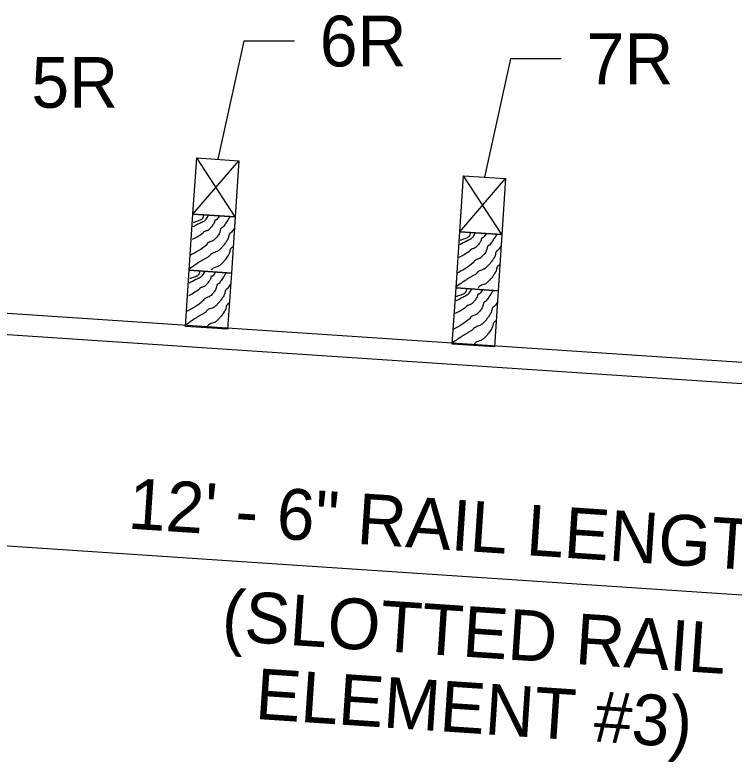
# Model space of a CAD drawing. Extents: x 1312564.2 to 1312581.5, y 1207298.4 to 1207352.6.
# Drawn here: x 1312568.33 to 1312569.46, y 1207300.555 to 1207301.729 of the extents above; entities that cross this region are included whole.
import ezdxf

# ---------------------------------------------------------------- set-up
doc = ezdxf.new("R2010")
doc.units = 0
for name, color, linetype in [('Level 13', 7, 'Continuous'), ('Level 14', 7, 'Continuous'), ('Level 15', 7, 'Continuous'), ('Level 20', 7, 'Continuous')]:
    doc.layers.add(name, color=color, linetype=linetype)

msp = doc.modelspace()

# ---------------------------------------------------------------- linework, layer by layer
at = {"layer": 'Level 13'}
for points in [[(1312568.6678214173, 1207301.4122627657), (1312568.6647315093, 1207301.4073251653), (1312568.6628659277, 1207301.4044208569), (1312568.6609422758, 1207301.4015529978), (1312568.6589786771, 1207301.3987138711), (1312568.6569932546, 1207301.3958957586), (1312568.656688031, 1207301.395570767), (1312568.6563126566, 1207301.3953208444), (1312568.655442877, 1207301.3949484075), (1312568.6545667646, 1207301.3945828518), (1312568.653867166, 1207301.3940285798), (1312568.6535256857, 1207301.3935333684), (1312568.6532358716, 1207301.393009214), (1312568.6527828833, 1207301.3918895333), (1312568.6521849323, 1207301.3894728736), (1312568.651619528, 1207301.3870258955), (1312568.6509438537, 1207301.3853195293), (1312568.6506328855, 1207301.3847958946), (1312568.6488896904, 1207301.3823134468), (1312568.646997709, 1207301.3799384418), (1312568.6449455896, 1207301.3776921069), (1312568.6427219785, 1207301.37559567), (1312568.6415729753, 1207301.3747528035), (1312568.64031552, 1207301.3740730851), (1312568.6376273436, 1207301.3729881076), (1312568.6349616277, 1207301.3719107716), (1312568.6337322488, 1207301.3712406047), (1312568.632622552, 1207301.3704111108), (1312568.6322004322, 1207301.369822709), (1312568.631907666, 1207301.369111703), (1312568.6315950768, 1207301.368420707), (1312568.6311134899, 1207301.367892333), (1312568.605108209, 1207301.351020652)], [(1312568.6509891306, 1207301.4133849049), (1312568.6466389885, 1207301.40711027), (1312568.6464051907, 1207301.4068910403), (1312568.6461016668, 1207301.4067649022), (1312568.645376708, 1207301.406669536), (1312568.644646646, 1207301.4065794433), (1312568.6440940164, 1207301.4062498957), (1312568.6439370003, 1207301.406016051), (1312568.6438069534, 1207301.40576809), (1312568.6436131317, 1207301.405237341), (1312568.6433881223, 1207301.4040892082), (1312568.6431848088, 1207301.402925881), (1312568.6430181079, 1207301.4023761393), (1312568.6427690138, 1207301.401867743), (1312568.6418760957, 1207301.4004513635), (1312568.640955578, 1207301.399046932), (1312568.638994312, 1207301.396310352), (1312568.635611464, 1207301.3925228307), (1312568.6349812, 1207301.3919432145), (1312568.6343288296, 1207301.3913813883), (1312568.6334191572, 1207301.3907523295), (1312568.6324297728, 1207301.3902670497), (1312568.6303230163, 1207301.3895434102), (1312568.6282308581, 1207301.38884164), (1312568.626805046, 1207301.38810779), (1312568.626586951, 1207301.3879555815), (1312568.6263755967, 1207301.387792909), (1312568.6258017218, 1207301.3871721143), (1312568.625310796, 1207301.386447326), (1312568.6247981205, 1207301.3857467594), (1312568.6241589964, 1207301.3851986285), (1312568.6083755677, 1207301.3760106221)], [(1312568.6341970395, 1207301.4145043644), (1312568.6326489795, 1207301.4122680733), (1312568.6323053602, 1207301.411755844), (1312568.6319701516, 1207301.4112295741), (1312568.629970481, 1207301.4080005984), (1312568.628432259, 1207301.406072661), (1312568.6265098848, 1207301.4046224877), (1312568.6201358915, 1207301.4013257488), (1312568.6095259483, 1207301.3958381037)], [(1312568.6262414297, 1207301.4150347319), (1312568.6258576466, 1207301.413280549), (1312568.6254319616, 1207301.411564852), (1312568.6248445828, 1207301.409997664), (1312568.6244528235, 1207301.4093041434), (1312568.6242258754, 1207301.4089859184), (1312568.624103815, 1207301.4088346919), (1312568.6240405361, 1207301.408761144), (1312568.6240083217, 1207301.408724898), (1312568.623992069, 1207301.4087069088), (1312568.6239757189, 1207301.4086890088), (1312568.6236720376, 1207301.4083758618), (1312568.6233514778, 1207301.4080782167), (1312568.6226630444, 1207301.4075263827), (1312568.621120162, 1207301.4065751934), (1312568.6175562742, 1207301.4051119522), (1312568.613709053, 1207301.403908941), (1312568.6118120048, 1207301.4032830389), (1312568.6100034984, 1207301.4025758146)], [(1312568.6746149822, 1207301.3942685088), (1312568.670203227, 1207301.3877948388), (1312568.6695430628, 1207301.3871295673), (1312568.6687308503, 1207301.3866053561), (1312568.6679130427, 1207301.386086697), (1312568.6672360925, 1207301.3854380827), (1312568.6666758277, 1207301.384494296), (1312568.6662763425, 1207301.3834678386), (1312568.6657599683, 1207301.3812651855), (1312568.6652874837, 1207301.3790266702), (1312568.6647216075, 1207301.377442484), (1312568.6644594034, 1207301.3769488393), (1312568.6613993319, 1207301.3720614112), (1312568.658031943, 1207301.3673980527), (1312568.6542742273, 1207301.3630273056), (1312568.6522230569, 1207301.3609730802), (1312568.6511498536, 1207301.3599825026), (1312568.650043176, 1207301.3590177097), (1312568.6486325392, 1207301.3580091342), (1312568.6471033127, 1207301.3572049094), (1312568.6438535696, 1207301.3559478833), (1312568.64062291, 1207301.3547233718), (1312568.6384103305, 1207301.3535115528), (1312568.6377402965, 1207301.3530081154), (1312568.6370218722, 1207301.3522464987), (1312568.6363961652, 1207301.3513699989), (1312568.6357506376, 1207301.3505138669), (1312568.6349727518, 1207301.3498133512), (1312568.6312491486, 1207301.3475299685), (1312568.6274406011, 1207301.3453683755), (1312568.6236415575, 1207301.34318748), (1312568.619946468, 1207301.3408461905), (1312568.6043086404, 1207301.3301578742)], [(1312569.070376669, 1207301.3854260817), (1312569.066026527, 1207301.379151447), (1312569.0657927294, 1207301.3789322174), (1312569.0654892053, 1207301.3788060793), (1312569.064764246, 1207301.378710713), (1312569.0640341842, 1207301.3786206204), (1312569.0634815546, 1207301.3782910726), (1312569.0633245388, 1207301.3780572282), (1312569.0631944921, 1207301.3778092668), (1312569.0630006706, 1207301.3772785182), (1312569.0627756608, 1207301.3761303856), (1312569.0625723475, 1207301.3749670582), (1312569.0624056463, 1207301.3744173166), (1312569.0621565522, 1207301.3739089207), (1312569.0612636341, 1207301.3724925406), (1312569.0603431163, 1207301.371088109), (1312569.0583818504, 1207301.3683515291), (1312569.0549990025, 1207301.364564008), (1312569.0543687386, 1207301.3639843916), (1312569.053716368, 1207301.3634225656), (1312569.0528066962, 1207301.3627935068), (1312569.0518173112, 1207301.3623082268), (1312569.0497105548, 1207301.3615845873), (1312569.0476183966, 1207301.3608828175), (1312569.0461925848, 1207301.360148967), (1312569.0459744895, 1207301.3599967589), (1312569.0457631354, 1207301.3598340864), (1312569.0451892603, 1207301.3592132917), (1312569.0446983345, 1207301.3584885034), (1312569.0441856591, 1207301.3577879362), (1312569.043546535, 1207301.3572398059), (1312569.0277631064, 1207301.3480517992)], [(1312569.0535845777, 1207301.3865455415), (1312569.0520365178, 1207301.3843092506), (1312569.0516928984, 1207301.3837970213), (1312569.0513576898, 1207301.3832707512), (1312569.0493580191, 1207301.3800417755), (1312569.0478197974, 1207301.3781138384), (1312569.0458974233, 1207301.3766636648), (1312569.0395234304, 1207301.373366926), (1312569.0289134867, 1207301.367879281)], [(1312569.0456289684, 1207301.3870759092), (1312569.045245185, 1207301.3853217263), (1312569.0448195, 1207301.383606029), (1312569.0442321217, 1207301.382038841), (1312569.043840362, 1207301.3813453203), (1312569.0436134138, 1207301.3810270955), (1312569.0434913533, 1207301.3808758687), (1312569.0434280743, 1207301.380802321), (1312569.0433958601, 1207301.3807660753), (1312569.0433796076, 1207301.3807480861), (1312569.0433632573, 1207301.3807301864), (1312569.043059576, 1207301.3804170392), (1312569.0427390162, 1207301.3801193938), (1312569.0420505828, 1207301.3795675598), (1312569.0405077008, 1207301.3786163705), (1312569.0369438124, 1207301.3771531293), (1312569.0330965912, 1207301.375950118), (1312569.0311995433, 1207301.375324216), (1312569.0293910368, 1207301.3746169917)], [(1312569.0872089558, 1207301.3843039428), (1312569.0841190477, 1207301.3793663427), (1312569.0822534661, 1207301.3764620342), (1312569.080329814, 1207301.373594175), (1312569.0783662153, 1207301.3707550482), (1312569.0763807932, 1207301.3679369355), (1312569.0760755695, 1207301.367611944), (1312569.0757001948, 1207301.3673620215), (1312569.0748304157, 1207301.3669895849), (1312569.0739543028, 1207301.3666240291), (1312569.0732547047, 1207301.3660697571), (1312569.0729132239, 1207301.3655745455), (1312569.07262341, 1207301.3650503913), (1312569.0721704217, 1207301.3639307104), (1312569.0715724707, 1207301.3615140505), (1312569.0710070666, 1207301.3590670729), (1312569.070331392, 1207301.3573607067), (1312569.070020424, 1207301.3568370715), (1312569.0682772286, 1207301.3543546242), (1312569.0663852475, 1207301.351979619), (1312569.0643331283, 1207301.3497332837), (1312569.0621095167, 1207301.3476368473), (1312569.0609605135, 1207301.3467939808), (1312569.0597030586, 1207301.3461142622), (1312569.0570148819, 1207301.3450292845), (1312569.0543491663, 1207301.3439519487), (1312569.053119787, 1207301.3432817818), (1312569.0520100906, 1207301.3424522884), (1312569.0515879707, 1207301.3418638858), (1312569.0512952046, 1207301.3411528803), (1312569.0509826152, 1207301.3404618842), (1312569.0505010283, 1207301.3399335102), (1312569.0244957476, 1207301.3230618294)], [(1312568.6726836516, 1207301.3652982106), (1312568.671964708, 1207301.364249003), (1312568.6716627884, 1207301.3638900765), (1312568.6713046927, 1207301.3635833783), (1312568.6704929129, 1207301.3630589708), (1312568.6696752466, 1207301.3625403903), (1312568.6693097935, 1207301.3622409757), (1312568.6689975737, 1207301.3618922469), (1312568.6684360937, 1207301.360949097), (1312568.6680360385, 1207301.3599229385), (1312568.6675198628, 1207301.3577201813), (1312568.66704837, 1207301.3554811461), (1312568.6667041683, 1207301.3544096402), (1312568.6662208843, 1207301.3534030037), (1312568.6654794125, 1207301.3521644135), (1312568.6647213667, 1207301.3509375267), (1312568.6597686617, 1207301.3438701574), (1312568.656007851, 1207301.3395016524), (1312568.6539655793, 1207301.3374409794), (1312568.6529004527, 1207301.3364445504), (1312568.651804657, 1207301.3354718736), (1312568.6503830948, 1207301.3344821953), (1312568.6488052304, 1207301.3337398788), (1312568.6454267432, 1207301.3326388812), (1312568.642161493, 1207301.331451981), (1312568.640725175, 1207301.3306022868), (1312568.6395017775, 1207301.3294622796), (1312568.6383078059, 1207301.3279585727)], [(1312569.094002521, 1207301.3663096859), (1312569.0895907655, 1207301.3598360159), (1312569.0889306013, 1207301.359170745), (1312569.088118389, 1207301.3586465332), (1312569.0873005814, 1207301.358127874), (1312569.086623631, 1207301.35747926), (1312569.0860633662, 1207301.3565354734), (1312569.085663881, 1207301.3555090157), (1312569.0851475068, 1207301.3533063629), (1312569.0846750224, 1207301.3510678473), (1312569.084109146, 1207301.3494836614), (1312569.0838469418, 1207301.3489900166), (1312569.08078687, 1207301.3441025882), (1312569.0774194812, 1207301.33943923), (1312569.0736617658, 1207301.335068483), (1312569.0716105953, 1207301.3330142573), (1312569.070537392, 1207301.3320236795), (1312569.0694307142, 1207301.3310588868), (1312569.068020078, 1207301.330050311), (1312569.066490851, 1207301.3292460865), (1312569.063241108, 1207301.3279890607), (1312569.0600104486, 1207301.326764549), (1312569.0577978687, 1207301.32555273), (1312569.0571278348, 1207301.3250492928), (1312569.056409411, 1207301.3242876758), (1312569.055783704, 1207301.3234111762), (1312569.055138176, 1207301.3225550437), (1312569.0543602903, 1207301.3218545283), (1312569.050636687, 1207301.3195711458), (1312569.0468281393, 1207301.3174095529), (1312569.043029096, 1207301.3152286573), (1312569.0393340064, 1207301.3128873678), (1312569.0236961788, 1207301.302199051)], [(1312568.6203561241, 1207301.3267541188), (1312568.619972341, 1207301.3249999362), (1312568.6195466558, 1207301.323284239), (1312568.6189592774, 1207301.3217170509), (1312568.6185675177, 1207301.3210235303), (1312568.6183405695, 1207301.3207053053), (1312568.6182185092, 1207301.3205540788), (1312568.6181552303, 1207301.320480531), (1312568.6181230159, 1207301.3204442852), (1312568.6181067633, 1207301.3204262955), (1312568.618090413, 1207301.3204083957), (1312568.6177867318, 1207301.3200952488), (1312568.617466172, 1207301.3197976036), (1312568.6167777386, 1207301.3192457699), (1312568.6152348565, 1207301.3182945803), (1312568.6116709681, 1207301.3168313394), (1312568.6078237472, 1207301.315628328), (1312568.605926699, 1207301.3150024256), (1312568.6041181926, 1207301.3142952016)], [(1312569.0920711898, 1207301.3373393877), (1312569.0913522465, 1207301.33629018), (1312569.0910503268, 1207301.3359312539), (1312569.0906922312, 1207301.3356245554), (1312569.0898804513, 1207301.335100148), (1312569.0890627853, 1207301.3345815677), (1312569.0886973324, 1207301.334282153), (1312569.0883851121, 1207301.3339334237), (1312569.0878236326, 1207301.3329902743), (1312569.087423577, 1207301.3319641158), (1312569.086907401, 1207301.3297613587), (1312569.0864359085, 1207301.3275223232), (1312569.0860917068, 1207301.3264508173), (1312569.0856084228, 1207301.3254441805), (1312569.0848669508, 1207301.3242055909), (1312569.0841089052, 1207301.3229787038), (1312569.0791562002, 1207301.3159113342), (1312569.0753953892, 1207301.3115428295), (1312569.0733531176, 1207301.3094821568), (1312569.072287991, 1207301.3084857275), (1312569.0711921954, 1207301.307513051), (1312569.0697706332, 1207301.3065233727), (1312569.068192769, 1207301.305781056), (1312569.0648142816, 1207301.304680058), (1312569.0615490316, 1207301.3034931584), (1312569.0601127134, 1207301.3026434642), (1312569.0588893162, 1207301.3015034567), (1312569.0576953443, 1207301.2999997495)], [(1312568.6619361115, 1207301.3239821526), (1312568.6588462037, 1207301.319044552), (1312568.6569806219, 1207301.3161402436), (1312568.65505697, 1207301.313272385), (1312568.6530933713, 1207301.310433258), (1312568.651107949, 1207301.3076151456), (1312568.6508027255, 1207301.3072901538), (1312568.6504273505, 1207301.3070402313), (1312568.6495575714, 1207301.306667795), (1312568.648681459, 1207301.3063022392), (1312568.6479818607, 1207301.3057479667), (1312568.6476403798, 1207301.3052527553), (1312568.647350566, 1207301.3047286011), (1312568.6468975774, 1207301.30360892), (1312568.6462996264, 1207301.3011922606), (1312568.6457342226, 1207301.2987452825), (1312568.6450585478, 1207301.297038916), (1312568.6447475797, 1207301.2965152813), (1312568.6430043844, 1207301.2940328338), (1312568.6411124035, 1207301.2916578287), (1312568.639060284, 1207301.2894114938), (1312568.636836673, 1207301.287315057), (1312568.6356876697, 1207301.2864721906), (1312568.6344302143, 1207301.2857924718), (1312568.6317420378, 1207301.2847074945), (1312568.629076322, 1207301.2836301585), (1312568.627846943, 1207301.2829599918), (1312568.6267372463, 1207301.2821304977), (1312568.626315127, 1207301.2815420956), (1312568.6260223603, 1207301.28083109), (1312568.6257097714, 1207301.280140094), (1312568.625228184, 1207301.2796117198), (1312568.5992229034, 1207301.2627400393)], [(1312568.6451038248, 1207301.3251042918), (1312568.6407536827, 1207301.318829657), (1312568.640519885, 1207301.3186104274), (1312568.6402163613, 1207301.3184842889), (1312568.6394914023, 1207301.3183889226), (1312568.6387613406, 1207301.3182988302), (1312568.6382087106, 1207301.3179692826), (1312568.6380516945, 1207301.3177354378), (1312568.637921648, 1207301.3174874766), (1312568.6377278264, 1207301.316956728), (1312568.6375028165, 1207301.3158085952), (1312568.6372995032, 1207301.314645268), (1312568.637132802, 1207301.3140955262), (1312568.6368837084, 1207301.31358713), (1312568.63599079, 1207301.3121707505), (1312568.6350702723, 1207301.310766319), (1312568.633109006, 1207301.3080297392), (1312568.6297261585, 1207301.304242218), (1312568.6290958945, 1207301.3036626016), (1312568.628443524, 1207301.303100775), (1312568.627533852, 1207301.3024717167), (1312568.6265444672, 1207301.3019864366), (1312568.6244377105, 1207301.3012627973), (1312568.6223455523, 1207301.3005610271), (1312568.6209197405, 1207301.2998271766), (1312568.6207016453, 1207301.2996749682), (1312568.6204902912, 1207301.299512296), (1312568.619916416, 1207301.2988915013), (1312568.6194254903, 1207301.298166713), (1312568.618912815, 1207301.2974661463), (1312568.6182736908, 1207301.2969180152), (1312568.6024902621, 1207301.287730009)], [(1312568.628311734, 1207301.326223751), (1312568.6267636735, 1207301.3239874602), (1312568.6264200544, 1207301.3234752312), (1312568.6260848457, 1207301.322948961), (1312568.624085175, 1207301.3197199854), (1312568.6225469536, 1207301.3177920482), (1312568.620624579, 1207301.316341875), (1312568.6142505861, 1207301.3130451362), (1312568.6036406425, 1207301.307557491)], [(1312568.6687296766, 1207301.305987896), (1312568.6643179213, 1207301.299514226), (1312568.663657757, 1207301.2988489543), (1312568.6628455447, 1207301.2983247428), (1312568.6620277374, 1207301.2978060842), (1312568.6613507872, 1207301.2971574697), (1312568.6607905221, 1207301.296213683), (1312568.6603910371, 1207301.2951872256), (1312568.6598746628, 1207301.2929845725), (1312568.6594021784, 1207301.2907460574), (1312568.658836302, 1207301.2891618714), (1312568.6585740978, 1207301.2886682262), (1312568.655514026, 1207301.2837807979), (1312568.6521466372, 1207301.27911744), (1312568.6483889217, 1207301.2747466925), (1312568.646337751, 1207301.2726924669), (1312568.645264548, 1207301.2717018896), (1312568.6441578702, 1207301.270737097), (1312568.6427472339, 1207301.2697285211), (1312568.6412180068, 1207301.2689242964), (1312568.6379682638, 1207301.2676672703), (1312568.6347376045, 1207301.2664427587), (1312568.6325250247, 1207301.2652309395), (1312568.631854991, 1207301.2647275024), (1312568.6311365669, 1207301.2639658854), (1312568.6305108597, 1207301.2630893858), (1312568.629865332, 1207301.2622332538), (1312568.629087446, 1207301.2615327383), (1312568.625363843, 1207301.2592493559), (1312568.6215552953, 1207301.2570877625), (1312568.6177562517, 1207301.2549068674), (1312568.614061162, 1207301.2525655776), (1312568.5984233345, 1207301.2418772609)], [(1312569.081323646, 1207301.2960233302), (1312569.078233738, 1207301.2910857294), (1312569.0763681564, 1207301.288181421), (1312569.0744445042, 1207301.2853135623), (1312569.0724809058, 1207301.2824744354), (1312569.0704954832, 1207301.279656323), (1312569.0701902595, 1207301.2793313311), (1312569.0698148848, 1207301.2790814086), (1312569.068945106, 1207301.278708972), (1312569.068068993, 1207301.2783434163), (1312569.0673693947, 1207301.2777891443), (1312569.067027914, 1207301.2772939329), (1312569.0667381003, 1207301.2767697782), (1312569.0662851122, 1207301.2756500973), (1312569.0656871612, 1207301.273233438), (1312569.0651217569, 1207301.27078646), (1312569.0644460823, 1207301.2690800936), (1312569.0641351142, 1207301.2685564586), (1312569.0623919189, 1207301.2660740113), (1312569.0604999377, 1207301.263699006), (1312569.0584478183, 1207301.2614526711), (1312569.0562242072, 1207301.259356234), (1312569.055075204, 1207301.258513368), (1312569.0538177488, 1207301.2578336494), (1312569.0511295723, 1207301.2567486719), (1312569.0484638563, 1207301.2556713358), (1312569.047234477, 1207301.2550011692), (1312569.0461247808, 1207301.2541716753), (1312569.0457026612, 1207301.253583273), (1312569.0454098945, 1207301.2528722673), (1312569.0450973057, 1207301.2521812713), (1312569.0446157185, 1207301.251652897), (1312569.0186104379, 1207301.2347812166)], [(1312569.0644913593, 1207301.297145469), (1312569.060141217, 1207301.2908708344), (1312569.0599074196, 1207301.2906516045), (1312569.0596038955, 1207301.2905254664), (1312569.0588789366, 1207301.2904301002), (1312569.058148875, 1207301.2903400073), (1312569.057596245, 1207301.2900104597), (1312569.057439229, 1207301.289776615), (1312569.0573091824, 1207301.2895286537), (1312569.0571153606, 1207301.2889979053), (1312569.056890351, 1207301.2878497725), (1312569.0566870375, 1207301.2866864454), (1312569.0565203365, 1207301.2861367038), (1312569.0562712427, 1207301.2856283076), (1312569.0553783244, 1207301.2842119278), (1312569.0544578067, 1207301.2828074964), (1312569.0524965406, 1207301.2800709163), (1312569.0491136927, 1207301.2762833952), (1312569.0484834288, 1207301.2757037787), (1312569.0478310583, 1207301.2751419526), (1312569.0469213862, 1207301.274512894), (1312569.0459320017, 1207301.274027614), (1312569.043825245, 1207301.2733039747), (1312569.0417330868, 1207301.2726022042), (1312569.0403072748, 1207301.2718683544), (1312569.0400891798, 1207301.2717161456), (1312569.0398778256, 1207301.2715534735), (1312569.0393039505, 1207301.2709326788), (1312569.0388130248, 1207301.2702078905), (1312569.0383003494, 1207301.2695073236), (1312569.037661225, 1207301.2689591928), (1312569.0218777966, 1207301.2597711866)], [(1312569.0476992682, 1207301.2982649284), (1312569.046151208, 1207301.2960286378), (1312569.0458075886, 1207301.2955164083), (1312569.04547238, 1207301.2949901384), (1312569.0434727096, 1207301.2917611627), (1312569.0419344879, 1207301.2898332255), (1312569.0400121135, 1207301.288383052), (1312569.0336381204, 1207301.2850863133), (1312569.023028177, 1207301.2795986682)], [(1312569.0397436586, 1207301.2987952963), (1312569.0393598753, 1207301.2970411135), (1312569.0389341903, 1207301.2953254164), (1312569.0383468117, 1207301.2937582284), (1312569.0379550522, 1207301.2930647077), (1312569.0377281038, 1207301.2927464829), (1312569.0376060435, 1207301.2925952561), (1312569.0375427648, 1207301.2925217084), (1312569.03751055, 1207301.2924854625), (1312569.0374942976, 1207301.292467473), (1312569.0374779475, 1207301.2924495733), (1312569.037174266, 1207301.292136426), (1312569.0368537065, 1207301.2918387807), (1312569.036165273, 1207301.291286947), (1312569.0346223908, 1207301.2903357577), (1312569.0310585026, 1207301.2888725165), (1312569.0272112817, 1207301.287669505), (1312569.0253142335, 1207301.287043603), (1312569.023505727, 1207301.2863363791)], [(1312568.666798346, 1207301.2770175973), (1312568.6660794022, 1207301.2759683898), (1312568.6657774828, 1207301.2756094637), (1312568.6654193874, 1207301.2753027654), (1312568.664607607, 1207301.2747783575), (1312568.663789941, 1207301.2742597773), (1312568.6634244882, 1207301.273960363), (1312568.663112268, 1207301.2736116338), (1312568.6625507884, 1207301.272668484), (1312568.6621507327, 1207301.2716423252), (1312568.661634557, 1207301.2694395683), (1312568.6611630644, 1207301.267200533), (1312568.6608188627, 1207301.2661290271), (1312568.6603355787, 1207301.2651223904), (1312568.6595941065, 1207301.2638838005), (1312568.6588360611, 1207301.2626569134), (1312568.653883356, 1207301.255589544), (1312568.6501225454, 1207301.2512210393), (1312568.6480802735, 1207301.2491603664), (1312568.6470151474, 1207301.2481639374), (1312568.6459193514, 1207301.2471912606), (1312568.644497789, 1207301.2462015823), (1312568.6429199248, 1207301.2454592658), (1312568.6395414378, 1207301.244358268), (1312568.6362761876, 1207301.243171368), (1312568.634839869, 1207301.2423216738), (1312568.6336164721, 1207301.2411816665), (1312568.6324225, 1207301.2396779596)], [(1312569.0881172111, 1207301.278029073), (1312569.0837054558, 1207301.271555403), (1312569.0830452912, 1207301.2708901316), (1312569.082233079, 1207301.2703659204), (1312569.0814152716, 1207301.2698472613), (1312569.0807383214, 1207301.269198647), (1312569.0801780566, 1207301.2682548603), (1312569.0797785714, 1207301.2672284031), (1312569.079262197, 1207301.2650257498), (1312569.0787897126, 1207301.2627872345), (1312569.0782238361, 1207301.2612030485), (1312569.077961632, 1207301.2607094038), (1312569.0749015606, 1207301.2558219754), (1312569.0715341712, 1207301.2511586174), (1312569.067776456, 1207301.24678787), (1312569.0657252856, 1207301.2447336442), (1312569.0646520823, 1207301.243743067), (1312569.0635454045, 1207301.242778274), (1312569.062134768, 1207301.2417696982), (1312569.060605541, 1207301.240965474), (1312569.0573557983, 1207301.2397084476), (1312569.0541251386, 1207301.238483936), (1312569.0519125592, 1207301.2372721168), (1312569.0512425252, 1207301.23676868), (1312569.0505241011, 1207301.2360070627), (1312569.0498983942, 1207301.2351305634), (1312569.0492528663, 1207301.2342744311), (1312569.0484749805, 1207301.2335739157), (1312569.0447513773, 1207301.231290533), (1312569.0409428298, 1207301.2291289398), (1312569.0371437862, 1207301.2269480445), (1312569.0334486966, 1207301.2246067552), (1312569.0178108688, 1207301.2139184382)], [(1312569.08618588, 1207301.2490587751), (1312569.0854669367, 1207301.2480095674), (1312569.085165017, 1207301.2476506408), (1312569.0848069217, 1207301.2473439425), (1312569.0839951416, 1207301.2468195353), (1312569.0831774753, 1207301.2463009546), (1312569.0828120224, 1207301.2460015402), (1312569.0824998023, 1207301.2456528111), (1312569.0819383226, 1207301.2447096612), (1312569.0815382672, 1207301.2436835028), (1312569.0810220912, 1207301.2414807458), (1312569.080550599, 1207301.2392417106), (1312569.080206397, 1207301.2381702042), (1312569.079723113, 1207301.2371635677), (1312569.078981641, 1207301.235924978), (1312569.0782235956, 1207301.234698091), (1312569.0732708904, 1207301.2276307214), (1312569.06951008, 1207301.2232622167), (1312569.0674678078, 1207301.221201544), (1312569.0664026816, 1207301.220205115), (1312569.0653068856, 1207301.2192324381), (1312569.0638853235, 1207301.2182427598), (1312569.062307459, 1207301.217500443), (1312569.058928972, 1207301.2163994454), (1312569.0556637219, 1207301.2152125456), (1312569.0542274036, 1207301.2143628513), (1312569.0530040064, 1207301.2132228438), (1312569.0518100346, 1207301.211719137)]]:
    msp.add_spline(points, degree=3, dxfattribs=at)
at = {"layer": 'Level 14'}
for p, q in [((1312568.6757792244, 1207301.4117322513), (1312568.615487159, 1207301.5044246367)), ((1312568.609601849, 1207301.416144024), (1312568.68166453, 1207301.5000128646)), ((1312569.0289893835, 1207301.3881852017), (1312569.1010520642, 1207301.472054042)), ((1312569.0951667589, 1207301.3837734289), (1312569.0348746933, 1207301.4764658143))]:
    msp.add_line(p, q, dxfattribs=at)
at = {"layer": 'Level 15'}
for p, q in [((1312568.6893766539, 1207301.6881581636), (1312568.6485758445, 1207301.5022187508)), ((1312568.7691052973, 1207301.6881581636), (1312568.6893766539, 1207301.6881581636)), ((1312569.1087641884, 1207301.6601993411), (1312569.0679633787, 1207301.474259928)), ((1312569.1884928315, 1207301.6601993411), (1312569.1087641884, 1207301.6601993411)), ((1312568.209466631, 1207301.2673344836), (1312575.5205605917, 1207300.7799342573)), ((1312568.207260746, 1207301.234245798), (1312575.5205605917, 1207300.7466985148)), ((1312568.186746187, 1207300.9032559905), (1312569.9194786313, 1207300.7877419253))]:
    msp.add_line(p, q, dxfattribs=at)
for points in [[(1312568.6757792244, 1207301.4117322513), (1312568.609601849, 1207301.416144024), (1312568.615487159, 1207301.5044246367), (1312568.68166453, 1207301.5000128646)], [(1312569.0951667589, 1207301.3837734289), (1312569.0289893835, 1207301.3881852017), (1312569.0348746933, 1207301.4764658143), (1312569.1010520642, 1207301.472054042)], [(1312568.6698939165, 1207301.3234516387), (1312568.6037165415, 1207301.327863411), (1312568.6096018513, 1207301.4161440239), (1312568.6757792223, 1207301.4117322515)], [(1312569.089281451, 1207301.295492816), (1312569.0231040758, 1207301.2999045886), (1312569.0289893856, 1207301.3881852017), (1312569.0951667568, 1207301.3837734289)], [(1312568.664008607, 1207301.2351710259), (1312568.5978312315, 1207301.2395827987), (1312568.6037165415, 1207301.327863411), (1312568.6698939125, 1207301.323451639)], [(1312569.0833961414, 1207301.2072122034), (1312569.017218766, 1207301.2116239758), (1312569.0231040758, 1207301.2999045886), (1312569.0892814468, 1207301.2954928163)]]:
    msp.add_lwpolyline(points, close=True, dxfattribs=at)

# ---------------------------------------------------------------- texts
at = {"layer": 'Level 20'}
for s, p in [('6R', (1312568.808969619, 1207301.6482938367)), ('7R', (1312569.2283571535, 1207301.6203350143)), ('5R', (1312568.3555168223, 1207301.5832920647))]:
    msp.add_text(s, height=0.07972865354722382, dxfattribs=at).set_placement(p)
for s, height, p in [('12\' - 6" RAIL LENGTH', 0.07972865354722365, (1312568.5061136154, 1207300.9217409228)), (' (SLOTTED RAIL ', 0.07972865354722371, (1312568.6238181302, 1207300.747824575)), (' ELEMENT #3)', 0.07972865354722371, (1312568.6765612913, 1207300.6244499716))]:
    msp.add_text(s, height=height, rotation=356.18597222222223, dxfattribs=at).set_placement(p)

doc.saveas('drawing.dxf')
